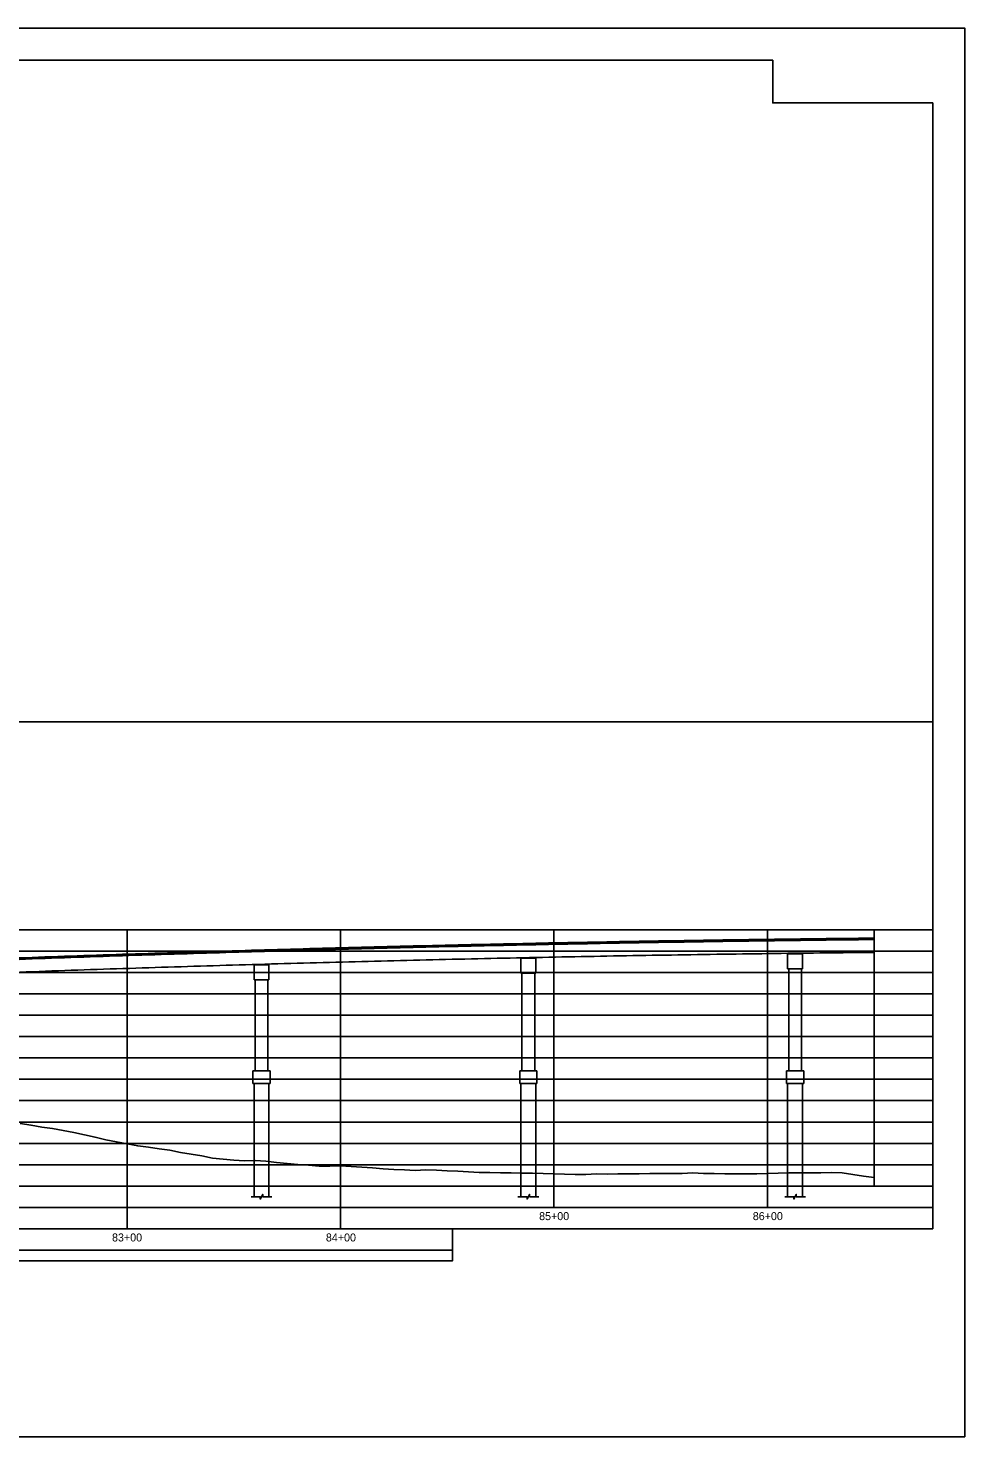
# Model space of a CAD drawing. Extents: x -464 to 4306, y -1372 to 300.
# Drawn here: x 1407 to 1846, y -1372 to -712 of the extents above; entities that cross this region are included whole.
import ezdxf

# ---------------------------------------------------------------- set-up
doc = ezdxf.new("R2010")
doc.units = 0
for name, color, linetype in [('BR_AUTO DIMENSION', 7, 'Continuous'), ('BR_BORDER LINES', 7, 'Continuous'), ('BR_GRID LINES', 7, 'Continuous'), ('BR_TEXT', 7, 'Continuous'), ('Mis Ground Lines', 7, 'Continuous'), ('NOPLOT', 7, 'Continuous'), ('Sheet Plot Border Outside CELL', 7, 'Continuous'), ('sub interior bent cap lines', 7, 'Continuous'), ('Sup Concrete Girder Lines', 7, 'Continuous'), ('Sup Concrete Slab Lines', 7, 'Continuous')]:
    doc.layers.add(name, color=color, linetype=linetype)

msp = doc.modelspace()

# ---------------------------------------------------------------- linework, layer by layer
at = {"layer": 'BR_AUTO DIMENSION'}
msp.add_line((1803.5, -1254.94), (1803.5, -1134.94), dxfattribs=at)
for points in [[(1511.62, -1259.94), (1515.94, -1259.94), (1515.94, -1261.06), (1517.06, -1258.83), (1517.06, -1259.94), (1521.37, -1259.94)], [(1636.62, -1259.94), (1640.94, -1259.94), (1640.94, -1261.06), (1642.06, -1258.83), (1642.06, -1259.94), (1646.37, -1259.94)], [(1761.62, -1259.94), (1765.94, -1259.94), (1765.94, -1261.06), (1767.06, -1258.83), (1767.06, -1259.94), (1771.37, -1259.94)]]:
    msp.add_lwpolyline(points, dxfattribs=at)
at = {"layer": 'BR_BORDER LINES'}
msp.add_line((826, -1037.44), (1831, -1037.44), dxfattribs=at)
at = {"layer": 'BR_GRID LINES'}
for p, q in [((826, -1134.94), (1831, -1134.94)), ((1453.5, -1274.94), (1453.5, -1134.94)), ((1553.5, -1274.94), (1553.5, -1134.94)), ((1653.5, -1264.94), (1653.5, -1134.94)), ((1753.5, -1264.94), (1753.5, -1134.94)), ((826, -1144.94), (1831, -1144.94)), ((826, -1154.94), (1831, -1154.94)), ((826, -1164.94), (1831, -1164.94)), ((826, -1174.94), (1831, -1174.94)), ((826, -1184.94), (1831, -1184.94)), ((826, -1194.94), (1831, -1194.94)), ((826, -1204.94), (1831, -1204.94)), ((826, -1214.94), (1831, -1214.94)), ((826, -1224.94), (1831, -1224.94)), ((826, -1234.94), (1831, -1234.94)), ((826, -1244.94), (1831, -1244.94)), ((826, -1254.94), (1831, -1254.94)), ((826, -1264.94), (1831, -1264.94)), ((826, -1274.94), (1606, -1274.94)), ((826, -1284.94), (1606, -1284.94))]:
    msp.add_line(p, q, dxfattribs=at)
at = {"layer": 'Mis Ground Lines'}
for points in [[(1403.5, -1225.59), (1408.5, -1226.47), (1413.5, -1227.29), (1418.5, -1228.04), (1423.5, -1228.92), (1428.5, -1229.85), (1433.5, -1230.95), (1438.5, -1232.11), (1443.5, -1233.26), (1448.5, -1234.29), (1453.5, -1235.24), (1458.5, -1236.14), (1463.5, -1236.8), (1468.5, -1237.44), (1473.5, -1238.09), (1478.5, -1239.16), (1483.5, -1239.94), (1488.5, -1240.85), (1493.5, -1241.83), (1498.5, -1242.32), (1503.5, -1242.77), (1508.5, -1243.11), (1513.5, -1243.04), (1518.5, -1243.31), (1523.5, -1243.88), (1528.5, -1244.46), (1533.5, -1244.85), (1538.5, -1245.2), (1543.5, -1245.56), (1548.5, -1245.68), (1553.5, -1245.55), (1558.5, -1245.79), (1563.5, -1246.13), (1568.5, -1246.45), (1573.5, -1246.84), (1578.5, -1247.25), (1583.5, -1247.39), (1588.5, -1247.62), (1593.5, -1247.42), (1598.5, -1247.57), (1603.5, -1247.75), (1608.5, -1247.97), (1613.5, -1248.34), (1618.5, -1248.59), (1623.5, -1248.64), (1628.5, -1248.75), (1633.5, -1248.82), (1638.5, -1248.88), (1643.5, -1248.94), (1648.5, -1249.02), (1653.5, -1249.27)], [(1653.5, -1249.27), (1658.5, -1249.43), (1663.5, -1249.55), (1668.5, -1249.46), (1673.5, -1249.28), (1678.5, -1249.35), (1683.5, -1249.27), (1688.5, -1249.19), (1693.5, -1249.21), (1698.5, -1249.12), (1703.5, -1249.06), (1708.5, -1249.14), (1713.5, -1249.14), (1718.5, -1248.83), (1723.5, -1249.01), (1728.5, -1249.08), (1733.5, -1249.2), (1738.5, -1249.2), (1743.5, -1249.23), (1748.5, -1249.19), (1753.5, -1249.12), (1758.5, -1248.93), (1763.5, -1248.78), (1768.5, -1248.78), (1773.5, -1248.69), (1778.5, -1248.71), (1783.5, -1248.67), (1788.5, -1248.8), (1793.5, -1249.46), (1798.5, -1250.25), (1803.5, -1250.87)]]:
    msp.add_lwpolyline(points, dxfattribs=at)
at = {"layer": 'NOPLOT'}
msp.add_lwpolyline([(871, -727.45), (871, -734.19), (826, -734.19), (826, -1357.44), (1371.93, -1357.44), (1371.93, -1289.94), (1606, -1289.94), (1606, -1274.94), (1831, -1274.94), (1831, -747.45), (1756, -747.45), (1756, -727.45)], close=True, dxfattribs=at)
at = {"layer": 'Sheet Plot Border Outside CELL'}
msp.add_lwpolyline([(766, -712.44), (1846, -712.44), (1846, -1372.44), (766, -1372.44)], close=True, dxfattribs=at)
at = {"layer": 'sub interior bent cap lines'}
for p, q in [((1645, -1148.19), (1638, -1148.34)), ((1638, -1148.34), (1638, -1155.26)), ((1645, -1148.19), (1645, -1155.26)), ((1770, -1146.16), (1763, -1146.24)), ((1763, -1146.24), (1763, -1153.2)), ((1770, -1146.16), (1770, -1153.2)), ((1520, -1151.26), (1513, -1151.46)), ((1513, -1151.46), (1513, -1158.36)), ((1520, -1151.26), (1520, -1158.36)), ((1763, -1153.2), (1770, -1153.2)), ((1763.5, -1153.2), (1763.5, -1200.94)), ((1769.5, -1153.2), (1769.5, -1200.94)), ((1513, -1158.36), (1520, -1158.36)), ((1513.5, -1158.36), (1513.5, -1200.94)), ((1519.5, -1158.36), (1519.5, -1200.94)), ((1638, -1155.26), (1645, -1155.26)), ((1638.5, -1155.26), (1638.5, -1200.94)), ((1644.5, -1155.26), (1644.5, -1200.94)), ((1512.5, -1200.94), (1520.5, -1200.94)), ((1512.5, -1200.94), (1512.5, -1206.94)), ((1520.5, -1200.94), (1520.5, -1206.94)), ((1637.5, -1200.94), (1645.5, -1200.94)), ((1637.5, -1200.94), (1637.5, -1206.94)), ((1645.5, -1200.94), (1645.5, -1206.94)), ((1762.5, -1200.94), (1770.5, -1200.94)), ((1762.5, -1200.94), (1762.5, -1206.94)), ((1770.5, -1200.94), (1770.5, -1206.94)), ((1512.5, -1206.94), (1520.5, -1206.94)), ((1513, -1206.94), (1513, -1259.94)), ((1520, -1206.94), (1520, -1259.94)), ((1637.5, -1206.94), (1645.5, -1206.94)), ((1638, -1206.94), (1638, -1259.94)), ((1645, -1206.94), (1645, -1259.94)), ((1762.5, -1206.94), (1770.5, -1206.94)), ((1763, -1206.94), (1763, -1259.94)), ((1770, -1206.94), (1770, -1259.94))]:
    msp.add_line(p, q, dxfattribs=at)
at = {"layer": 'Sup Concrete Girder Lines'}
for points in [[(1348.53, -1150.81), (1372.73, -1149.86), (1396.92, -1148.95), (1421.12, -1148.08), (1445.32, -1147.25), (1469.52, -1146.45), (1493.72, -1145.7), (1517.92, -1144.98), (1542.12, -1144.31), (1566.32, -1143.67), (1590.52, -1143.07), (1614.71, -1142.51), (1638.91, -1141.98), (1663.11, -1141.5), (1687.31, -1141.05), (1711.51, -1140.65), (1735.71, -1140.28), (1759.91, -1139.95), (1784.11, -1139.66), (1803.54, -1139.45)], [(1348.76, -1156.81), (1372.96, -1155.86), (1397.15, -1154.95), (1421.33, -1154.08), (1445.52, -1153.25), (1469.71, -1152.45), (1493.9, -1151.7), (1518.09, -1150.98), (1542.28, -1150.3), (1566.47, -1149.67), (1590.66, -1149.07), (1614.85, -1148.5), (1639.04, -1147.98), (1663.23, -1147.5), (1687.42, -1147.05), (1711.61, -1146.65), (1735.8, -1146.28), (1759.99, -1145.95), (1784.17, -1145.66), (1803.54, -1145.45)]]:
    msp.add_spline(points, degree=3, dxfattribs=at)
at = {"layer": 'Sup Concrete Slab Lines'}
msp.add_spline([(1348.5, -1150.14), (1372.7, -1149.2), (1396.9, -1148.29), (1421.1, -1147.41), (1445.3, -1146.58), (1469.5, -1145.79), (1493.7, -1145.03), (1517.9, -1144.32), (1542.1, -1143.64), (1566.3, -1143), (1590.5, -1142.4), (1614.7, -1141.84), (1638.9, -1141.32), (1663.1, -1140.83), (1687.3, -1140.39), (1711.5, -1139.98), (1735.7, -1139.61), (1759.9, -1139.28), (1784.1, -1138.99), (1803.54, -1138.79)], degree=3, dxfattribs=at)

# ---------------------------------------------------------------- texts
at = {"layer": 'BR_TEXT'}
for s, p in [('85+00', (1646.55, -1270.91)), ('86+00', (1746.66, -1270.91)), ('83+00', (1446.46, -1280.91)), ('84+00', (1546.66, -1280.91))]:
    msp.add_text(s, height=3.75, rotation=360, dxfattribs=at).set_placement(p)

doc.saveas('drawing.dxf')
